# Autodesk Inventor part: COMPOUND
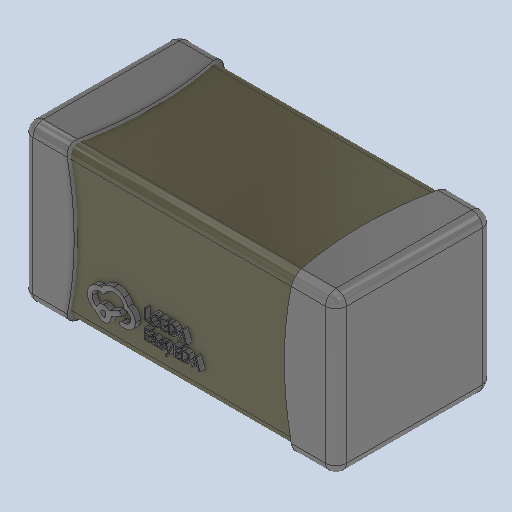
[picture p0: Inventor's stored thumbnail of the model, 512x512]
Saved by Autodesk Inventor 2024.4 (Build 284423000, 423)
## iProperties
Created: 2025-05
Part Number: COMPOUND
Material: Generic
Document SubType Name: Modeling
Designer: AdminForWorker
Density: 1 g/cm^3
Appearance: Default
Title: COMPOUND (3)
Author: AdminForWorker
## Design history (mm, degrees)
feature "Body1"
feature "Body2"
feature "Body3"
body "Solid1"
body "Solid2"
body "Solid3"
